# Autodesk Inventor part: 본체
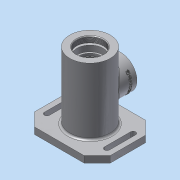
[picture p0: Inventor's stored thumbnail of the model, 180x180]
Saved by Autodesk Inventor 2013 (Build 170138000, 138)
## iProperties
Created: 2017-10
Part Number: 본체
Material: 알루미늄 6061
Document SubType Name: Modeling
Designer: dgall
Mass: 740.706 g
Surface Area: 652.711 cm^2
Volume: 273.323 cm^3
Density: 2.71 g/cm^3
Author: dgall
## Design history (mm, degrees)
sketch "스케치1"
  geometry: C1 r 31 at (0, 0); 1 further point
  constraints: 1 centre point, 1 coincident
  dimensions: "d0" = 62 diameter of C1
extrude "돌출1" new body sketch "스케치1" distance "d1" = 102; taper "d2" = 0 deg
sketch "스케치2"
  geometry: L1 (-58, 47)-(58, 47); L2 (58, 47)-(58, -47); L3 (58, -47)-(-58, -47); L4 (-58, -47)-(-58, 47); C1 r 31 at (0, 0) reference; C2 r 35 at (0, 0); 2 further points
  constraints: 8 end point, 2 midpoint, 2 parallel, 1 centre point, 1 coincident, 1 horizontal, 1 horizontal alignment, 1 perpendicular, 1 vertical alignment
  dimensions: "d3" = 94 distance of L1.end L2.end; "d5" = 116 distance of L2.end L3.end; "d6" = 70 diameter of C2
extrude "돌출2" join sketch "스케치2" distance "d7" = 10; taper "d8" = 0 deg
extrude "돌출3" join sketch "스케치2" distance "d9" = 13; taper "d10" = 0 deg
chamfer "모따기1" distance "d11" = 20; stored, may be unused: second distance "d12" = 2, angle "d13" = 45 deg
sketch "스케치3"
  geometry: L1 (31, 102)-(-31, 102) reference; L2 (-31, 0)-(31, 0) reference; L3 (-35, -13)-(35, -13) reference; L4 (35, -10)-(-35, -10) reference; L5 (47, -10)-(27, -10) reference; L6 (27, -10)-(27, 0) reference; L7 (27, 0)-(47, 0) reference; L8 (47, 0)-(47, -10) reference; L9 (27, -10)-(27, 0) reference; L10 (-27, -10)-(27, -10) reference; L11 (-27, 0)-(-27, -10) reference; L12 (27, 0)-(-27, 0) reference; L13 (-27, -10)-(-47, -10) reference; L14 (-47, -10)-(-47, 0) reference; L15 (-47, 0)-(-27, 0) reference; L16 (-27, 0)-(-27, -10) reference; L17 (31, 0)-(31, 102) reference; L18 (-31, 0)-(-31, 102) reference; L19 (31, 71)-(47, 71); L20 (47, 71)-(47, 21); L21 (47, 21)-(31, 21); L22 (31, 71)-(18, 71); L23 (18, 71)-(18, 21); L24 (18, 21)-(31, 21); L25 (47, 46)-(18, 46); 1 further point
  constraints: 14 end point, 4 perpendicular, 2 midpoint, 2 parallel, 2 point on line
  dimensions: "d14" = 56 distance from line of L1 L25.start; "d15" = 50 distance of L19.end L20.end; "d16" = 47 distance from line of point (0, 0) L20; "d17" = 13 distance of L23.end L21.end
revolve "회전1" sketch "스케치3" stored, may be unused: angle "d18" = 90 deg
sketch "스케치4"
  geometry: L1 (47, -10)-(27, -10) reference; L2 (27, -10)-(27, 0) reference; L3 (27, 0)-(47, 0) reference; L4 (47, 0)-(47, -10) reference; L5 (27, -10)-(27, 0) reference; L6 (-27, -10)-(27, -10) reference; L7 (-27, 0)-(-27, -10) reference; L8 (27, 0)-(-27, 0) reference; L9 (-27, -10)-(-47, -10) reference; L10 (-47, -10)-(-47, 0) reference; L11 (-47, 0)-(-27, 0) reference; L12 (-27, 0)-(-27, -10) reference; L13 (31, 102)-(-31, 102) reference; L14 (31, 0)-(31, 102) reference; L15 (-31, 0)-(-31, 102) reference; L16 (31, 71)-(47, 71) reference; L17 (47, 21)-(47, 71) reference; L18 (31, 21)-(47, 21) reference; L19 (12.904, 1)-(12.5, 1.7); L20 (12.5, 1.7)-(12.5, 8.3); L21 (12.5, 8.3)-(10, 8.3); L22 (10, 8.3)-(10, 11); L23 (10, 11)-(16.5, 11); L24 (16.5, 11)-(16.5, 16); L25 (16.5, 16)-(17.5, 16); L26 (17.5, 16)-(17.5, 27); L27 (17.5, 27)-(26, 27); L28 (26, 27)-(26, 65); L29 (26, 65)-(17.5, 65); L30 (17.5, 65)-(17.5, 76); L31 (17.5, 76)-(18.5, 76); L32 (18.5, 76)-(18.5, 77.75); L33 (18.5, 77.75)-(17.5, 77.75); L34 (17.5, 77.75)-(17.5, 81); L35 (17.5, 81)-(20, 81); L36 (20, 81)-(20, 90); L37 (20, 90)-(24, 90); L38 (24, 90)-(24, 93); L39 (24, 93)-(0, 93); L40 (0, 93)-(0, -13); L41 (-35, -13)-(35, -13) reference; L42 (12.904, 1)-(16, 1); L43 (16, 1)-(22, -13); L44 (22, -13)-(0, -13); 2 further points
  constraints: 50 end point, 11 parallel, 11 perpendicular, 1 midpoint, 1 point on line, 1 vertical alignment
  dimensions: "d31" = 25 diameter of L20 L40; "d32" = 20 diameter of L22 L40; "d34" = 30 deg angle of L20 L19; "d35" = 7.3 vertical distance of L19.start L20.end; "d36" = 2.7 distance between parallel lines of L23 L21; "d37" = 24 distance between parallel lines of L41 L23; "d38" = 5 distance of L23.end L24.end; "d39" = 33 diameter of L24 L40; "d40" = 11 distance of L25.end L26.end; "d41" = 35 diameter of L26 L40; "d42" = 52 diameter of L28 L40; "d43" = 35 diameter of L30 L40; "d44" = 11 distance between parallel lines of L31 L29; "d45" = 26 distance between parallel lines of L13 L31; "d46" = 21 distance between parallel lines of L13 L35; "d47" = 3 distance of L37.end L38.end; "d48" = 12 distance between parallel lines of L13 L37; "d49" = 48 diameter of L38 L40; "d50" = 40 diameter of L36 L40; "d51" = 35 diameter of L34 L40; "d52" = 1.75 distance of L31.end L32.end; "d53" = 37 diameter of L32 L40; "d54" = 32 diameter of L42.end L40; "d55" = 0.7 vertical distance of L19.start L19.end; "d56" = 44 diameter of L43.end L40
revolve "회전2" sketch "스케치4" stored, may be unused: angle "d57" = 90 deg
hole "구멍1" diameter "d60" = 32; stored, may be unused: countersink angle "d64" = 90 deg, drill point angle "d66" = 0 deg; dims "d58" = 10, "d59" = 10, "d61" = 6, "d62" = 4, "d63" = 2, "d65" = 47
hole "구멍2" diameter "d69" = 40.376; stored, may be unused: countersink angle "d73" = 90 deg, drill point angle "d75" = 0 deg; dims "d67" = 10, "d68" = 10, "d70" = 9, "d71" = 4, "d72" = 2, "d74" = 9
sketch "스케치5"
  geometry: L1 (38, 47)-(-38, 47) reference; L2 (-50, -20)-(-50, 20); L3 (-42, 20)-(-42, -20); L4 (42, -20)-(42, 20); L5 (50, 20)-(50, -20); C1 r 31 at (0, 0) reference; A1 r 4 centre (-46, 20) between (-42, 20) and (-50, 20); A2 r 4 centre (-46, -20) between (-50, -20) and (-42, -20); A3 r 4 centre (46, 20) between (50, 20) and (42, 20); A4 r 4 centre (46, -20) between (42, -20) and (50, -20)
  constraints: 8 end point, 8 point on circle, 8 tangent, 4 centre point, 3 parallel, 2 horizontal alignment, 1 equal radius, 1 perpendicular
  dimensions: "d76" = 40 distance of A2.centre A1.centre; "d78" = 4 radius of A1; "d79" = 20 vertical distance of A2.centre C1.centre; "d80" = 46 horizontal distance of C1.centre A2.centre; "d81" = 46 horizontal distance of C1.centre A4.centre
extrude "돌출4" cut sketch "스케치5" distance "d82" = 13; taper "d83" = 0 deg
sketch "스케치6"
  geometry: C1 r 16 at (0, 0) reference; 2 further points
  constraints: 1 horizontal alignment
  dimensions: "d84" = 20.5 distance of C1.centre point (-20.5, 0)
hole "구멍3" sketch "스케치6" at (-20.5, 0) diameter "d85" = 2.459; stored, may be unused: countersink angle "d89" = 90 deg, drill point angle "d91" = 118 deg; dims "d86" = 6, "d87" = 4, "d88" = 2, "d90" = 8
fillet "모깎기1" dims "d95" = 0.3
fillet "모깎기2" dims "d96" = 3
fillet "모깎기3" dims "d97" = 3
chamfer "모따기2" distance "d98" = 1; stored, may be unused: second distance "d99" = 2, angle "d100" = 45 deg
chamfer "모따기3" distance "d101" = 1; stored, may be unused: second distance "d102" = 2, angle "d103" = 45 deg
fillet "모깎기4" dims "d104" = 3
fillet "모깎기5" dims "d105" = 3
chamfer "모따기4" distance "d106" = 1; stored, may be unused: second distance "d107" = 2, angle "d108" = 45 deg
node "작업축1"
node "작업 평면1"
node "작업 평면2"
sketch "스케치7"
  geometry: L1 (8, -25)-(8, 25) reference; 3 further points
  constraints: 1 horizontal alignment, 1 midpoint, 1 other
  dimensions: "d109" = 10 distance from line of L1 point (-2, 0)
feature "엠보싱1" sketch "스케치7" dims "d110" = 0.5, "d111" = 0
node "솔리드1"
pattern_circular "원형 패턴1" dims angle "d93" = 360 deg
node "투영된 루프1"
node "투영된 루프2"
node "투영된 루프3"
node "투영된 루프4"
node "투영된 루프5"
node "투영된 루프6"
node "투영된 루프7"
node "투영된 루프8"
